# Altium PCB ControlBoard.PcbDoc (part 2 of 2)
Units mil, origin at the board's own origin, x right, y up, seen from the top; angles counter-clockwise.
Board outline 2798 x 1675 mil, 4 copper layers (Top Layer, Layer 1, Layer 2, Bottom Layer), stack 62.493 mil thick; 143 components, 84 nets, 457 pads, 255 vias.
Unrouted connection lines stored in the file: 49.
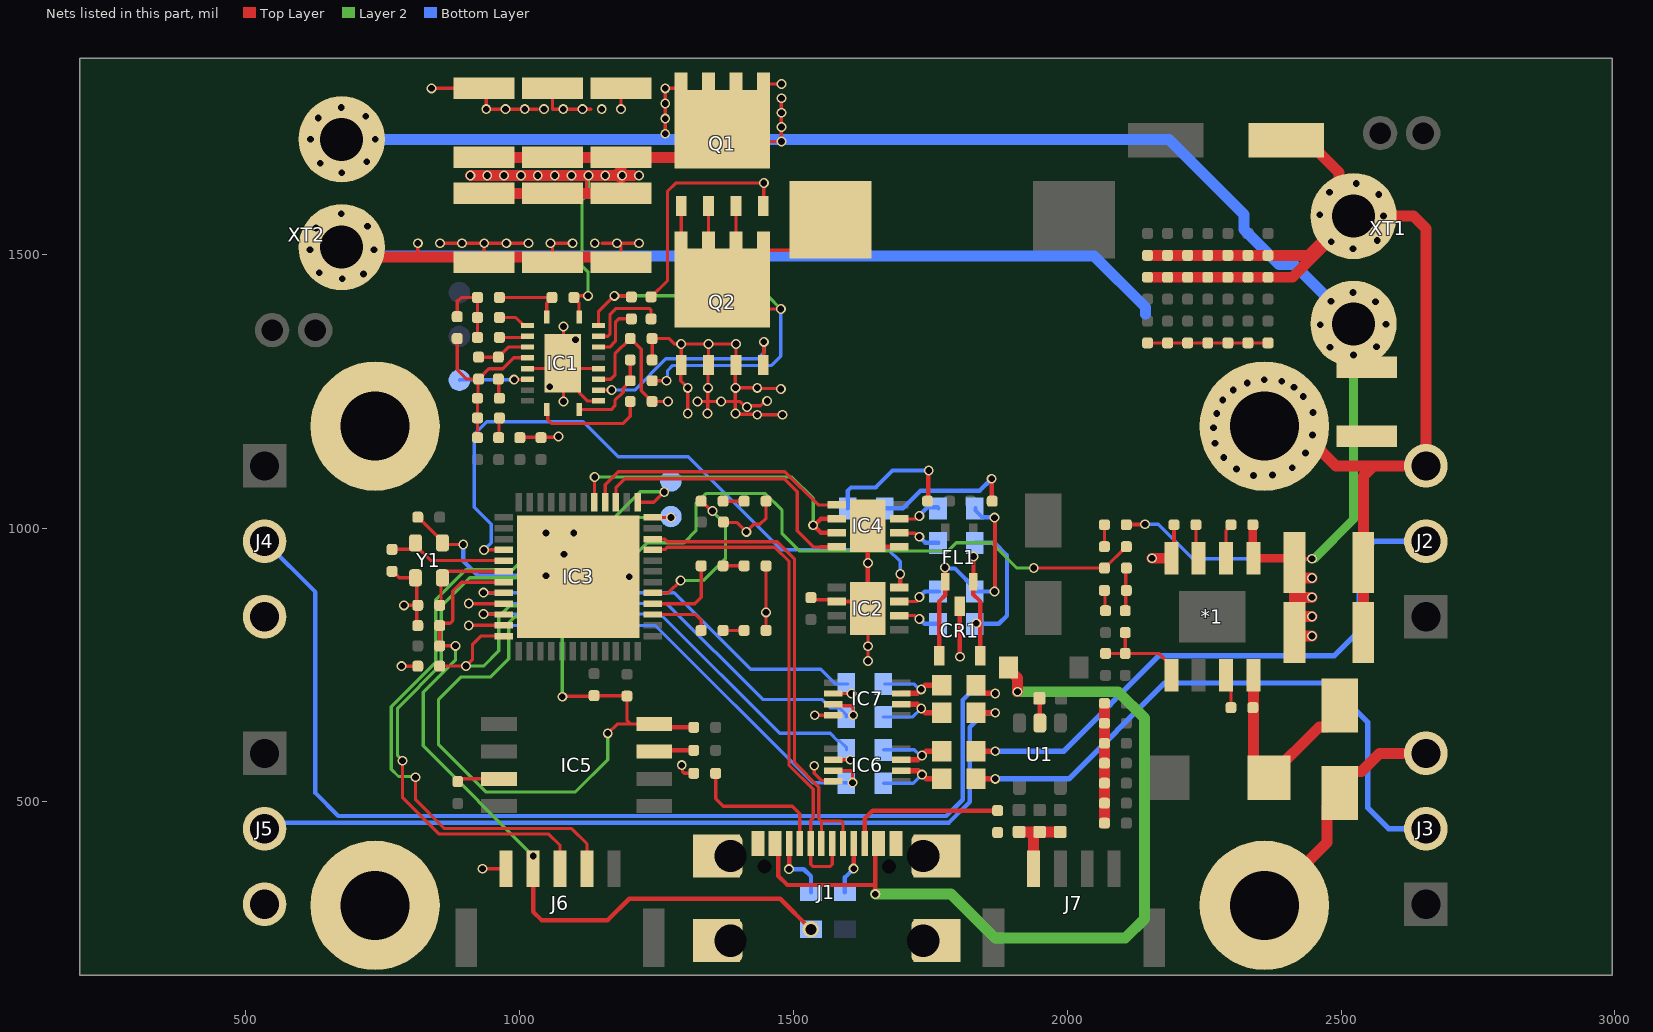
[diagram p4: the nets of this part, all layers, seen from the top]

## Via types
v1: diameter 18, hole 12.3, Top Layer to Bottom Layer, tented both sides, 252 vias
v2: diameter 30, hole 20, Top Layer to Bottom Layer, 2 vias
v3: diameter 20, hole 12.3, Top Layer to Bottom Layer, tented both sides, 1 vias

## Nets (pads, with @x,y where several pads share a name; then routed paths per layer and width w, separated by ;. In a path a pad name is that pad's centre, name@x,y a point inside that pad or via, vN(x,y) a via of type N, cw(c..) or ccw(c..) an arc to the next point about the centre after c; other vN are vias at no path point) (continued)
GND: *1.4 C2.1 C3.1 C5.1 C6.1 C7.1 C8.1 C9.1 C10.1 C11.1 C12.1 C13.1 C14.1 C15.1 C16.1 C17.1 C18.1 C21.1 C24.2 C25.2 C26.1 C27.1 C28.1 C29.1 C30.1 C31.1 C32.1 C33.1 C34.1 C35.1 C36.1 C37.1 C38.1 C39.1 C40.1 C41.1 C42.1 C43.1 C44.1 C45.1 C46.1 C47.2 C48.2 C49.2 C50.2 C51.2 C52.2 C53.2 C54.1 C55.1 C56.1 C57.1 C58.1 C59.2 C60.2 C61.1 C62.2 CR1.3 D2.1 D4.2 D5.2 D6.2 IC1.6 IC1.12 IC1.15 IC1.21 IC2.2 IC2.9 IC3.49 IC4.5 IC4.9 IC5.4 IC6.4 IC7.4 J1.1 J1.2 J1.3 J1.4 J1.17 J1.18 J1.19 J1.20 J2.3 J3.3 J4.3 J5.3 J6.1 J7.1 pad.7 Q2.1 Q2.2 Q2.3 R3.1 R4.2 R5.2 R7.2 R11.2 R13.2 R16.1 R20.1 R23.1 R33.2 U1.2 XT1.2 XT2.2 Y1.2 Y1.4 | length 13063.8
  Top Layer w6: v1(617,1508) 622,1513 XT2.2@663,1513 ; v1(628,1548) XT2.2@663,1513 ; v1(634,1466) XT2.2@675,1507 ; v1(674,1574) 675,1573 XT2.2@675,1513 ; v1(676,1455) 675,1456 XT2.2@675,1504 ; v1(715,1464) XT2.2@675,1504 ; v1(722,1551) XT2.2@684,1513 ; v1(734,1508) 729,1513 XT2.2@684,1513 ; C55.1@767,921 768.08,921 780.08,909 Y1.4@809.79,909 811.89,906.89 C54.1@811.89,858.78 ; v1(784.22,747.78) C62.2@814,747.78 ; v1(788.78,858.78) C54.1@811.89,858.78 ; C59.2@814,821.78 811.89,823.89 C54.1@811.89,858.78 ; C54.1@814,858.78 C54.1@811.89,858.78 ; C52.2@814,1019.78 814.97,1019.78 859,975.75 Y1.2@859,972.78 861.78,970 v1(897,970) ; 814.15,1494.69 v1@814.15,1515.15 ; v1(838.98,1802.98) C12.1@935,1802.98 939,1798.98 v1(939,1765) 1032,1765 ; v1@856,1520 v1@1012,1520 ; R13.2@886,1386 886,1414 893,1421 R7.2@923,1421 R11.2@923,1384.5 C21.1@923,1348 ; v1(932.13,377.87) J6.1@975.36,377.87 ; v1@935,1517 935,1494.69 C14.1@935,1485.01 938,1488.01 C14.1@938,1494.69 ; C61.1@1000.33,1165 1001.33,1166 1070,1166 v1(1071,1167) ; IC1.6@1014.04,1291.16 1069.16,1291.16 IC1.21@1079,1301 ; v1(1055,1258) IC1.21@1079,1282 ; C16.1@1060,1485.01 1060,1494.69 v1@1060,1519 ; v1@1060,1520 v1@1100,1520 ; 1060,1765 1130,1765 ; 1060,1767 C13.1@1060,1802.98 ; v1(1078,692) 1079,693 1135,693 C58.1@1136,694 1136.5,693.5 1195.5,693.5 C57.1@1196,693 1196,649 1203,642 ; v1(1080,1231) IC1.21@1080,1300 ; v1(1080,1368) IC1.21@1080,1322 ; v1(1102,1344) IC1.21@1080,1322 ; IC3.49@1107,911 v1(1200,911) ; IC1.12@1143.96,1232.1 1123.15,1232.1 1109.46,1245.79 1109.46,1270.54 IC1.21@1088.84,1291.16 ; IC1.15@1143.96,1291.16 IC1.21@1088.84,1291.16 ; 1151,1520 v1@1185,1520 ; v1(1161,625) 1178,642 1203,642 ; C15.1@1185,1485.01 v1@1185,1520 ; v1@1185,1766 C18.1@1185,1802.98 ; v1(1218,1520) v1@1185,1520 ; C51.2@1242,1307 C24.2@1242,1346 1273,1346 1283,1336 v1(1295,1336) ; IC5.4@1245.73,642 1203,642 ; Q2.1@1294,1289 1294,1269 v1(1307,1256) v1(1307,1209) ; Q2.1@1294,1297 Q2.1@1295,1298 v1(1295,1336) ; v1(1296,567) 1297.32,565.68 1297.32,555.51 1300.84,552 R23.1@1318,552 ; v1(1325,1231) 1343.5,1231 ; v1(1343,1209) 1343.5,1209.5 1343.5,1231 ; v1(1344,1256) 1343.5,1255.5 1343.5,1231 ; v1@1344,1259 1344,1297 Q2.2@1345,1298 v1(1345,1336) ; C56.1@1372,1010 1397,1010 v1(1414,993) 1427.65,1006.65 1438.65,1006.65 1450,1018 D4.2@1450,1049 ; v1(1394,1209) 1395,1208 1433,1208 v1(1434,1207) v1(1480,1207) ; v1@1394,1214 1394,1231 ; Q2.3@1394,1291 v1(1394,1256) ; Q2.3@1394,1297 Q2.3@1395,1298 1395,1332.49 1391.49,1336 v1(1345,1336) ; D6.2@1450,813 v1(1450,846) D5.2@1450,931 ; v1(1452,1232) 1448.75,1232 1439.85,1223.1 1417.1,1223.1 v1(1415,1221) 1412.49,1221 1402.49,1231 1394,1231 ; v1(1477,1254) 1476,1255 1435,1255 v1(1434,1256) v1(1394,1256) ; C53.2@1532,872 1535.1,868.9 1575.81,868.9 IC2.2@1578.91,865.8 ; v1(1538,566) 1538,552 1551,539 1571.46,539 IC6.4@1572.99,537.47 ; v1(1539,658) 1539.24,658.24 1572.28,658.24 1572.52,658 IC7.4@1572.99,658.47 ; v1(1636,757) v1(1636,784) IC2.9@1636,853 ; R5.2@2106,849 2107,850 2107,926 R33.2@2108,927 ; C36.1@2146.67,1338 C44.1@2183.33,1338 C45.1@2220,1338 C35.1@2256.67,1338 C33.1@2293.33,1338 C34.1@2330,1338 C46.1@2366.67,1338 ; v1(2267,1183) 2270,1186 pad.7@2296,1186 ; v1(2270,1155) pad.7@2301,1186 ; v1(2273,1209) pad.7@2296,1186 ; v1(2284,1234) pad.7@2332,1186 ; v1(2286,1129) pad.7@2343,1186 ; v1(2303,1252) pad.7@2360,1195 ; v1(2309,1108) 2309,1135 pad.7@2360,1186 ; v1(2329,1265) pad.7@2360,1234 ; v1(2360,1271) pad.7@2360,1236 ; v1(2392,1268) pad.7@2360,1236 ; v1(2414,1257) pad.7@2360,1203 ; v1(2431,1240) 2414,1240 pad.7@2360,1186 ; pad.7@2442,1217 pad.7@2411,1186 ; v1(2449,1211) 2424,1186 2418.51,1186 pad.7@2411,1186 ; v1(2461,1572) 2463.31,1569.69 2512.44,1569.69 XT1.2@2522.31,1569.69 ; v1(2479,1613) 2496.27,1595.73 XT1.2@2522.31,1569.69 ; v1(2482,1523) XT1.2@2522.83,1563.83 ; v1(2522,1510) 2522.83,1510.83 XT1.2@2522.83,1563.83 ; v1(2528,1629) 2522.83,1623.83 XT1.2@2522.83,1569.69 ; v1(2566,1525) XT1.2@2522.83,1568.17 ; v1(2569,1609) XT1.2@2529.69,1569.69 ; v1(2577.57,1569.69) XT1.2@2529.69,1569.69 ; XT2.2@663,1513 XT2.2@675,1513 ; XT2.2@675,1504 XT2.2@675,1507 ; XT2.2@675,1507 XT2.2@675,1513 ; XT2.2@675,1513 XT2.2@684,1513 ; IC1.21@1079,1301 1080,1302 IC1.21@1080,1322 ; IC1.21@1079,1301 IC1.21@1080,1300 ; IC1.21@1080,1300 IC1.21@1088.84,1291.16 ; v1(1295,1336) v1(1345,1336) ; 1343.5,1231 v1(1368,1231) 1390,1231 1394,1231 ; 1394,1231 1394,1235 v1(1394,1256) ; pad.7@2296,1186 pad.7@2301,1186 ; pad.7@2301,1186 pad.7@2332,1186 ; pad.7@2332,1186 pad.7@2343,1186 ; pad.7@2343,1186 pad.7@2360,1186 ; pad.7@2360,1186 pad.7@2411,1186 ; pad.7@2360,1186 pad.7@2360,1195 ; pad.7@2360,1195 pad.7@2360,1203 ; pad.7@2360,1203 pad.7@2360,1234 ; pad.7@2360,1234 pad.7@2360,1236 ; XT1.2@2522.31,1569.69 XT1.2@2522.83,1569.69 ; XT1.2@2522.83,1563.83 XT1.2@2522.83,1568.17 ; XT1.2@2522.83,1568.17 XT1.2@2522.83,1569.69 ; XT1.2@2522.83,1569.69 XT1.2@2529.69,1569.69
  Top Layer w8: IC5.4@1245.73,642 1251.73,636 C60.2@1318,636 ; IC2.2@1578.91,865.8 1635.2,865.8 IC2.9@1636,865 ; IC2.9@1636,853 IC2.9@1636,865 ; IC4.9@1636,1004 IC4.9@1636,994.09 ; IC4.5@1693.09,965.61 1664.48,965.61 IC4.9@1636,994.09 ; v1(1804,765) CR1.3@1804,857.25 ; C50.2@1949,689 1949.5,688.5 1949.5,644.56 U1.2@1950,644.06 ; *1.4@2190,944.77 2195,949.77 R4.2@2195,1006 ; IC2.9@1636,865 v1(1636,936) IC4.9@1636,994.09
  Top Layer w20: XT2.2@675,1513 693.31,1494.69 814.15,1494.69 935,1494.69 938,1494.69 1060,1494.69 1175.31,1494.69 C15.1@1185,1485.01 ; C49.2@1912,445 1930.75,445 ; J7.1@1938.18,377.87 1938.18,437.57 1930.75,445 ; C48.2@1987,445 C47.2@1949.5,445 1930.75,445 ; C5.1@2068,461 C6.1@2068,497.5 C7.1@2068,534 C8.1@2068,570.5 C9.1@2068,607 C10.1@2068,643.5 C11.1@2068,680 ; C43.1@2146.67,1458 C42.1@2183.33,1458 C41.1@2220,1458 C40.1@2256.67,1458 C39.1@2293.33,1458 C38.1@2330,1458 C37.1@2366.67,1458 2411.14,1458 2445.94,1492.8 2479.07,1525.93 2517.64,1564.5 XT1.2@2522.83,1569.69 2517.64,1574.89 2496.53,1596 2496.53,1649.11 2437.64,1708 C25.2@2400.24,1708 ; C26.1@2146.67,1498 C27.1@2183.33,1498 C28.1@2220,1498 C29.1@2256.67,1498 C30.1@2293.33,1498 C31.1@2330,1498 C32.1@2366.67,1498 2440.75,1498 2473.87,1531.13 XT1.2@2512.44,1569.69 ; v1(2154.77,944.77) *1.4@2190,944.77 ; pad.7@2360,311 2474.54,425.54 2474.54,492.52 D2.1@2498,515.98 2498,531.73 2521.46,555.2 2537.21,555.2 2570.61,588.59 J3.3@2655,588.59 ; pad.7@2418.51,1186 2441.25,1163.25 2490.92,1113.59 2559.59,1113.59 ; C2.1@2540.99,809 C3.1@2540.99,937 2540.99,1094.99 2559.59,1113.59 ; v1(2577.57,1569.69) 2632.31,1569.69 2655,1547 J2.3@2655,1113.59 2559.59,1113.59
  Layer 2 w6: v1(1078,692) 1078,828 1068,838 991,838 980,827 980,761 947,728 893,728 852,687 852,604 938,518 1102,518 1161,577 v1(1161,625) ; v1(2340,1096) pad.7@2360,1116 ; v1(2375,1097) 2360,1112 pad.7@2360,1116 ; v1(2411,1110) pad.7@2360,1161 ; v1(2435,1137) pad.7@2386,1186 ; v1(2448,1170) 2432,1186 pad.7@2386,1186 ; pad.7@2360,1116 pad.7@2360,1161 ; pad.7@2360,1161 pad.7@2360,1186 pad.7@2386,1186
  Bottom Layer w8: v1(897,970) 897,940 924,913 v1(1048,913) 1048,952 ; v1(1081,952) 1048,952 ; v1(1099,991) v1(1048,991) 1048,952
  Bottom Layer w20: XT2.2@675,1513 691.1,1496.9 2049.1,1496.9 2142.9,1403.1 2142.9,1390.43 ; pad.7@2298.5,1247.5 pad.7@2360,1186
  other v1: 1395,1336 814.15,1520 854.54,1520 894.92,1520 935.31,1520 975.69,1520 1016.08,1520 1056.46,1520 1096.85,1520 1137.23,1520 1177.61,1520 974.14,1765 1009.29,1765 1044.43,1765 1079.57,1765 1114.71,1765 1149.86,1765 1185,1765
LM5146_VCC: C24.1 IC1.14 R15.1 | length 272.6
  Top Layer w6: IC1.14@1143.96,1271.47 1166.47,1271.47 1174,1279 1174,1318 C24.1@1202,1346 1202.5,1346 1222,1326.5 1222,1251 R15.1@1242,1231 v1(1271,1231)
Net*1_2: *1.2 R1.2 | length 65
  Top Layer w6: *1.2@2290,944.77 2290,995.92 2299,1004.92 R1.2@2299,1006
Net*1_3: *1.3 R4.1 | length 63.3
  Top Layer w6: R4.1@2235,1006 2235,949.77 *1.3@2240,944.77
Net*1_5: *1.5 C4.1 R2.2 R5.1 | length 184.6
  Top Layer w6: R2.2@2070,771 C4.1@2106,771 ; R5.1@2106,809 C4.1@2106,771 ; *1.5@2190,731.23 2190,748.45 2167.45,771 C4.1@2106,771
Net*1_7: *1.7 C1.2 | length 63
  Top Layer w6: *1.7@2290,731.23 2299,722.23 C1.2@2299,672
Net*1_8: *1.8 C1.1 D2.2 L1.1 | length 393
  Top Layer w20: *1.8@2340,731.23 2340,572.52 L1.1@2368.52,544 2368.52,544.98 2460.34,636.8 2474.54,636.8 2498,660.27 D2.2@2498,676.02
NetC19_1: C19.1 IC1.17 | length 98.9
  Top Layer w6: IC1.17@1143.96,1330.53 1164.53,1330.53 1175,1341 1175,1376 1181,1382 C19.1@1201,1382
NetC19_2: C19.2 IC1.19 L2.1 Q1.1 Q1.2 Q1.3 Q2.5 Q2.6 Q2.7 Q2.8 Q2.9 R14.2 | length 1328.8
  Top Layer w6: IC1.19@1143.96,1369.9 1143.96,1394.96 v1(1173,1424) 1199,1424 C19.2@1201,1422 ; R14.2@1242,1269 v1(1268,1269) ; Q2.8@1295,1525.87 Q1.1@1295,1588 ; Q2.7@1345,1525.87 Q1.2@1345,1588 ; Q2.9@1361.2,1447 Q2.9@1370,1438.2 ; Q2.6@1395,1525.87 Q1.3@1395,1588 ; v1(1477,1400) 1408.2,1400 Q2.9@1370,1438.2 ; L2.1@1567.56,1563 1511.7,1507.15 1438.95,1507.15 Q2.9@1370,1438.2
  Layer 2 w6: v1(1173,1424) 1453,1424 v1(1477,1400)
  Bottom Layer w6: v1(1268,1269) 1270,1271 1270,1287 1280,1297 1460,1297 1477,1314 v1(1477,1400)
NetC20_1: C20.1 C23.1 IC1.5 R9.2 R12.2 R13.1 | length 316
  Top Layer w6: R13.1@886,1346 886,1289 903,1272 C23.1@925,1272 ; R9.2@923,1165 C20.1@923,1201 R12.2@923,1237 924,1238 924,1271 C23.1@925,1272 ; IC1.5@1014.04,1310.84 988.84,1310.84 969,1291 944,1291 C23.1@925,1272
NetC20_2: C20.2 R8.2 | length 36.6
  Top Layer w6: R8.2@961.67,1165 962.33,1165.67 962.33,1200.33 C20.2@963,1201
NetC21_2: C21.2 IC1.3 | length 52
  Top Layer w6: C21.2@963,1348 1004.94,1348 1007.15,1350.21 IC1.3@1014.04,1350.21
NetC22_1: C22.1 R12.1 | length 35.8
  Top Layer w6: C22.1@961,1272 962,1271 962,1238 R12.1@963,1237
NetC22_2: C22.2 C23.2 IC1.4 | length 96.7
  Top Layer w6: C23.2@925,1312 C22.2@961,1312 979.53,1330.53 IC1.4@1014.04,1330.53
NetC51_1: C51.1 IC1.11 R14.1 | length 164.7
  Top Layer w6: IC1.11@1108.53,1216.35 1167.35,1216.35 1174,1223 1174,1233 1189,1248 1189,1254.92 1203,1268.92 1202,1269.92 C51.1@1202,1307
NetCR1_1: CR1.1 FL1.1 SB2.2 SB4.2 | length 458.3
  Top Layer w8: CR1.1@1766.6,766.75 1766.6,866.6 1777.2,877.2 FL1.1@1777.2,901.93 ; v1(1777,928) 1777.2,927.8 FL1.1@1777.2,901.93 ; FL1.1@1777.41,901.72 FL1.1@1777.2,901.93 ; v1(1867,884) 1868,885 1868,1018 v1@1869,1019
  Bottom Layer w8: v1(1777,928) 1778.91,926.09 1794.91,926.09 1833,888 1833,884 v1(1867,884) ; SB4.2@1832.5,1036 1832.5,1032 1844.5,1020 1868,1020 v1@1869,1019
  other v1: 1867,1019
NetCR1_2: CR1.2 FL1.2 SB3.2 SB5.2 | length 436.3
  Top Layer w8: v1(1829,948) 1828.8,947.8 1828.8,901.93 FL1.2@1828.59,901.72 1828.59,878.41 1841.4,865.6 v1@1841.4,827 ; v1(1834,826) 1835,827 v1@1841.4,827 ; CR1.2@1841.4,766.75 v1@1841.4,827
  Bottom Layer w8: SB3.2@1831.5,825 1875,825 1890,840 1890,950 1867,973 SB5.2@1832.5,973
NetD1_2: D1.2 R3.2 | length 37.8
  Top Layer w6: R3.2@2068,886 2069,885 2069,850 D1.2@2070,849
NetD4_1: D4.1 R21.2 | length 38.5
  Top Layer w6: R21.2@1371.5,1049 D4.1@1410,1049
NetD5_1: D5.1 R22.2 | length 38.5
  Top Layer w6: R22.2@1371.5,931 D5.1@1410,931
NetD6_1: D6.1 R24.2 | length 38.5
  Top Layer w6: R24.2@1371.5,813 D6.1@1410,813
NetIC1_1: IC1.1 R6.1 R7.1 | length 135.3
  Top Layer w6: R7.1@963,1421 R6.1@1059,1421 1059,1419.92 1049.47,1410.39 IC1.1@1049.47,1385.65
NetIC1_2: IC1.2 R11.1 | length 57.1
  Top Layer w6: R11.1@963,1384.5 992.55,1384.5 1007.15,1369.9 IC1.2@1014.04,1369.9
NetIC1_7: IC1.7 TP5.1 | length 125.2
  Top Layer w6: v1(990,1271) 990.24,1271.24 1013.8,1271.24 IC1.7@1014.04,1271.47
  Bottom Layer w6: TP5.1@890,1270 890,1271 v1(990,1271)
NetIC1_10: IC1.10 R15.2 | length 205.3
  Top Layer w6: IC1.10@1049.47,1216.35 1051.39,1214.43 1051.39,1197.61 1056.02,1192.98 1058,1191 1189,1191 1202,1204 R15.2@1202,1231
NetIC1_13: IC1.13 Q2.4 | length 392.7
  Top Layer w6: IC1.13@1143.96,1251.79 1144.07,1251.89 1167.89,1251.89 v1(1168,1252) ; Q2.4@1445,1298 1446,1299 v1(1446,1340)
  Bottom Layer w6: v1(1168,1252) 1210,1252 1267,1309 1435,1309 1446,1320 v1(1446,1340)
NetIC1_18: IC1.18 R10.2 | length 155.2
  Top Layer w6: IC1.18@1143.96,1350.21 1161.39,1350.21 1164.9,1353.73 1164.9,1389.9 1176,1401 1236.49,1401 1240,1397.49 R10.2@1240,1382
NetIC2_6: IC2.6 SB3.1 | length 77.2
  Top Layer w6: IC2.6@1693.09,840.2 1721.8,840.2 1728,834 v1(1730,834)
  Bottom Layer w8: v1(1730,834) 1730.31,834 1739.31,825 SB3.1@1764,825
NetIC2_7: IC2.7 SB2.1 | length 81.7
  Top Layer w6: IC2.7@1693.09,865.8 1724.8,865.8 1730,871 v1(1730,874)
  Bottom Layer w8: v1(1730,874) 1740,884 SB2.1@1765.5,884
NetIC3_27: IC3.27 R24.1 | length 111.6
  Top Layer w6: IC3.27@1242.83,842.1 1320.9,842.1 1331.5,831.5 R24.1@1331.5,813
NetIC3_28: IC3.28 R22.1 | length 151
  Top Layer w6: IC3.28@1242.83,861.79 1319.79,861.79 1331.5,873.5 R22.1@1331.5,931
NetIC3_29: IC3.29 R21.1 | length 283.4
  Top Layer w6: IC3.29@1242.83,881.47 1271.47,881.47 v1(1294,904) ; R21.1@1331.5,1049 1332.58,1049 1350.58,1031 v1(1352,1031)
  Layer 2 w6: v1(1294,904) 1335,904 1376,945 1376,1007 v1(1352,1031)
NetIC4_6: IC4.6 SB5.1 | length 79.5
  Top Layer w6: IC4.6@1693.09,991.2 1693.69,990.6 1722.15,990.6 1728.75,984 v1(1730,984)
  Bottom Layer w8: v1(1730,984) 1741,973 SB5.1@1765,973
NetIC4_7: IC4.7 SB4.1 | length 82.6
  Top Layer w6: IC4.7@1693.09,1016.8 1693.48,1016.4 1724.15,1016.4 1729.75,1022 v1(1730,1022)
  Bottom Layer w8: v1(1730,1022) 1730,1023.31 1744.69,1038 1763,1038 SB4.1@1765,1036
NetIC5_3: IC5.3 R26.1 | length 73.1
  Top Layer w8: IC5.3@1245.73,592 1247.73,594 R26.1@1318,594
NetIC5_7: IC5.7 R25.1 | length 77.3
  Top Layer w6: R25.1@887,537 892,542 IC5.7@962.27,542
NetJ1_7: J1.7 SB7.1 | length 121.2
  Top Layer w8: v1(1492,377) 1492.05,377.05 J1.7@1492.1,423.8 J1.7@1492.1,423.8
  Bottom Layer w8: v1(1492,377) 1519,377 1532,364 SB7.1@1532,335
NetJ1_8: J1.8 R23.2 | length 265.7
  Top Layer w6: R23.2@1358,552 1358,506 1372,492 1498,492 1511.79,478.21 J1.8@1511.79,423.8
NetJ1_13: J1.13 SB6.1 | length 95.5
  Top Layer w8: v1(1610,378) 1610.11,378.11 1610.11,423.7 J1.13@1610.21,423.8
  Bottom Layer w8: SB6.1@1594,335 1594,362 v1(1610,378)
NetJ1_14: J1.14 R20.2 | length 294.5
  Top Layer w8: J1.14@1629.9,423.8 1629.9,468.9 1645,484 R20.2@1873,484
NetJ2_2: J2.2 R27.2 | length 1060.6
  Top Layer w10: R27.2@1833.5,592.33 v1(1868.67,592.33)
  Bottom Layer w10: v1(1868.67,592.33) 1993.33,592.33 2168,767 2488,767 2533,812 2533,949 2559.8,975.8 J2.2@2655,975.8
NetJ3_2: J3.2 R28.2 | length 1092
  Top Layer w10: R28.2@1833.5,542 v1@1865,542
  Bottom Layer w10: v1(1868.67,542) 2003,542 2178,717 2477,717 2549,645 2549,489 2587.2,450.8 J3.2@2655,450.8
NetJ4_2: J4.2 R29.2 | length 1997.4
  Top Layer w10: R29.2@1833.5,713 1833.5,712.72 1848.21,698 v1@1868,698
  Bottom Layer w8: J4.2@534.25,975.8 627,883.05 627,516 668.81,474.19 1779.19,474.19 1809,504 1809,686 1821,698 v1(1868.67,698)
NetJ5_2: J5.2 R30.2 | length 1536.1
  Top Layer w10: R30.2@1833.5,662.67 v1@1867.67,662.67
  Bottom Layer w8: J5.2@534.25,450.8 545.55,462.09 766.91,462.09 1784.2,462.09 1822,499.89 1822,636 1847.67,661.67 1867.67,661.67 v1(1868.67,662.67)
NetQ1_4: Q1.4 R10.1 | length 430.1
  Top Layer w6: R10.1@1240,1422 1270,1452 1270,1615 1285,1630 v1(1446,1630) 1446,1589 Q1.4@1445,1588
NetR17_2: R17.2 SB1.1 | length 258.6
  Top Layer w8: v1(1862,1090) 1862.5,1089.5 1862.5,1049.5 R17.2@1862.9,1049.1
  Bottom Layer w8: SB1.1@1667,1036 1700,1036 1732,1068 1840,1068 v1(1862,1090)
NetR18_1: R18.1 SB1.2 | length 260.9
  Top Layer w8: R18.1@1745,1049 1746,1050 1746,1104 v1(1747,1105)
  Bottom Layer w8: SB1.2@1599.5,1036 1599.5,1068.36 1605.14,1074 1650,1074 1681,1105 ; 1690,1105 1681,1105 ; v1(1747,1105) 1681,1105
NetR31_2: R31.2 R32.1 | length 40
  Top Layer w6: R32.1@2068,966 R31.2@2068,1006
RESET: C59.1 IC3.7 J6.2 R19.2 SB7.2 | length 1371
  Top Layer w6: v1(882.78,784.78) R19.2@854,784.78 C59.1@854,821.78 858.22,826 873,826 878,831 878,885 894.16,901.16 IC3.7@971.17,901.16
  Top Layer w8: J6.2@1024.57,377.87 1024.57,299.43 1040,284 1161,284 1200,323 1476,323 v2(1532,267)
  Layer 2 w6: v1(882.78,784.78) 882.78,758.78 824,700 824,602 v1(1025,401)
  Bottom Layer w8: v2(1532,267) SB7.2@1532,267.5
RS485_DIR: IC3.41 IC4.2 IC4.3 | length 606.6
  Top Layer w6: IC3.41@1136.53,1046.83 1136.76,1047.06 1136.76,1092.76 v1(1137,1093)
  Top Layer w8: v1(1536,1005) v1@1536.39,1005 ; IC4.3@1578.91,991.2 1550.18,991.2 v1@1536.39,1005 ; IC4.2@1578.91,1016.8 1578.81,1016.9 1550.18,1016.9 1538.28,1005 v1@1536.39,1005
  Layer 2 w6: v1(1137,1093) 1497,1093 1536,1054 v1(1536,1005)
RS485_RX: IC3.40 IC4.1 | length 490.2
  Top Layer w6: IC3.40@1156.21,1046.83 1156.21,1079.21 1180,1103 1484.28,1103 1545.09,1042.19 IC4.1@1578.72,1042.19
  Top Layer w8: IC4.1@1578.72,1042.19 IC4.1@1578.91,1042.39
RS485_TX: IC3.39 IC4.4 | length 530.1
  Top Layer w6: IC3.39@1175.9,1046.83 1175.9,1073.9 1192,1090 1483,1090 1507,1066 1507,995 1536.69,965.31 1549,965.31
  Top Layer w8: 1549,965.31 1578.61,965.31 IC4.4@1578.91,965.61
STB_1: IC2.8 IC3.4 | length 1207
  Top Layer w6: v1(935,960) 935.11,960.11 971.07,960.11 IC3.4@971.17,960.21
  Top Layer w8: IC2.8@1693.09,891.39 1695,893.3 v1(1695,916)
  Bottom Layer w6: v1(935,960) 948,973 948,1007 917,1038 917,1171 939.9,1193.9 1115.82,1193.9 1179.72,1130 1308,1130 1477.5,960.5 1673.5,960.5 1695,939 v1(1695,916)
SWCLK: IC3.37 J6.4 TP6.1 | length 1381.7
  Top Layer w6: v1(810,545) 810,504 862.8,451.2 1094.8,451.2 1123,423 J6.4@1123,377.87 ; IC3.37@1215.27,1046.83 1244.83,1046.83 v1(1264,1066)
  Layer 2 w6: v1(810,545) 808.77,546.23 778.77,546.23 765.49,559.51 765.49,673.49 847,755 847,869 902,924 987,924 1031.1,968.1 1122.1,968.1 1220,1066 v1(1264,1066)
SWDIO: IC3.36 J6.3 TP7.1 | length 1280.6
  Top Layer w6: v1(786,575) 786,508 852.9,441.1 1052.9,441.1 1073.79,420.21 J6.3@1073.79,377.87 ; IC3.36@1242.83,1019.27 v1(1276.27,1019.27)
  Layer 2 w6: v1(786,575) 786,575.51 777,584.51 777,670.72 857.1,750.82 857.1,856.82 909.28,909 993,909 1016,932 1116,932 1203.27,1019.27 v1(1276.27,1019.27)
  Bottom Layer w6: v1(1276.27,1019.27) 1279.51,1019.27 TP7.1@1283.19,1022.94
USB_CAN_DM: IC3.33 J1.9 J1.11 | length 916
  Top Layer w6: IC3.33@1242.83,960.21 1243.26,960.65 1265.04,960.65 1269.29,964.9 1466.1,964.9 1491.9,939.1 1491.9,566.82 1536,522.72 1536,470.81 1531.47,466.28 J1.9@1531.47,423.8 1531.47,385.51 1534.99,382 1567.33,382 1570.84,385.51 J1.11@1570.84,423.8
USB_CAN_DP: IC3.34 J1.10 J1.12 | length 892.6
  Top Layer w6: IC3.34@1242.83,979.9 1265.37,979.9 1270.27,975 1470.28,975 1502,943.28 1502,571 1546.1,526.9 1546.1,469.97 1551.16,464.91 ; J1.10@1551.16,423.8 1551.16,464.91 ; J1.12@1590.53,423.8 1590.53,461.4 1587.01,464.91 1551.16,464.91
V_POWER_IN: C62.1 IC3.12 R32.2 R33.1 | length 1669.9
  Top Layer w6: C62.1@852.24,748 v1(902,748) 914,760 914,788 928.73,802.73 IC3.12@971.17,802.73 ; v1(1939,927) 2036,927 R33.1@2068,927 2068.5,927 2107.5,966 R32.2@2108,966
  Layer 2 w6: v1(902,748) 934,748 962,776 962,838 982,858 1118,858 1233,973 1300.24,973 1322,994.76 1322,1044.76 1340.24,1063 1449,1063 1479,1033 1479,990.5 1511.5,958 1782,958 1797,973 1862,973 1908,927 v1(1939,927)
VBUS: D3.1 J1.5 J1.6 J1.15 J1.16 | length 1556.3
  Top Layer w6: J1.5@1460.61,423.8 J1.6@1472.42,423.8
  Top Layer w8: J1.6@1472.42,423.8 1472.42,364.58 1489,348 1649.58,348 ; v1(1649.58,331.42) J1.15@1649.58,423.8
  Top Layer w20: D3.1@1892.63,745 1892.63,742.24 1909,725.87 v1(1909,701)
  Layer 2 w20: v1(1649.58,331.42) 1787.58,331.42 1868,251 2106,251 2141,286 2141,653 2093,701 v1(1909,701)
VIN: *1.1 C2.2 C3.2 C12.2 C13.2 C14.2 C15.2 C16.2 C17.2 C18.2 IC1.20 Q1.5 Q1.6 Q1.7 Q1.8 Q1.9 R1.1 R6.2 R31.1 XT1.1 XT2.1 | length 6271.8
  Top Layer w6: v1(632,1749) 635.85,1749 XT2.1@635.85,1666.15 ; XT2.1@675,1708 XT2.1@675.93,1708.93 ; XT2.1@675,1709.85 XT2.1@675.93,1708.93 ; v1(719,1752) 678.35,1711.35 XT2.1@675.93,1708.93 ; v1(721,1669) 715.85,1669 XT2.1@675.93,1708.93 ; IC1.20@1108.53,1385.65 1108.53,1410.39 1099,1419.92 R6.2@1099,1421 1102,1424 v1(1125,1424) ; v1@1122,1641 1122.5,1640.5 1122.5,1610.99 ; C15.2@1185,1610.99 v1@1185,1639.15 ; v1(1266,1720) v1(1266,1803) 1266.13,1803.13 1286.19,1803.13 1295,1811.94 Q1.8@1295,1815.87 ; Q1.9@1370,1728.2 1392.2,1706 v1(1478,1706) v1@1478,1782 ; Q1.5@1445,1815.87 1449.87,1811 v1(1478,1811) ; C3.2@2415.01,937 2422.01,944 v1(2447.01,944) ; v1(2462,1371) 2474.67,1371 XT1.1@2497.83,1347.84 ; XT1.1@2466.84,1372.84 2466.84,1374.84 XT1.1@2493.84,1401.84 ; XT1.1@2474.67,1372.84 XT1.1@2522.83,1372.84 ; v1(2479.99,1330) XT1.1@2497.83,1347.84 ; v1(2481.68,1414) XT1.1@2493.84,1401.84 ; v1(2522,1430) XT1.1@2493.84,1401.84 ; XT1.1@2522.83,1316 2522.83,1294.27 C17.2@2523,1294.1 ; XT1.1@2522.83,1322.67 XT1.1@2522.83,1322.83 ; v1(2523,1316) 2523,1322.67 XT1.1@2522.83,1322.83 ; v1(2562.99,1413) XT1.1@2522.83,1372.84 ; v1(2564.68,1331) XT1.1@2522.83,1372.84 ; v1(2582,1372) 2581.16,1372.84 XT1.1@2522.83,1372.84 ; XT1.1@2493.84,1401.84 XT1.1@2522.83,1372.84 ; XT1.1@2497.83,1347.84 XT1.1@2522.83,1322.83 ; XT1.1@2497.83,1347.84 XT1.1@2522.83,1372.84 ; XT1.1@2522.83,1322.83 XT1.1@2522.83,1372.84
  Top Layer w8: R31.1@2108,1006 2108.5,1006.5 2141.5,1006.5 v1(2142,1007)
  Top Layer w16: R1.1@2339,1006 2339,945.77 *1.1@2340,944.77 C3.2@2407.24,944.77
  Top Layer w20: v1(617.85,1709.85) 617.85,1684.15 v1(636,1666) ; XT2.1@635.85,1666.15 v1(636,1666) ; v1(674,1768) 675,1767 675,1714.7 678.35,1711.35 679.85,1709.85 v1(736.15,1709.85) ; v1(675,1649) 658,1666 v1(636,1666) ; XT2.1@675,1705 v1(636,1666) ; v1(910,1644) 1175.77,1644 ; C14.2@935,1610.99 C16.2@1060,1610.99 1122.5,1610.99 C15.2@1185,1610.99 ; C12.2@935,1677 C13.2@1060,1677 C18.2@1185,1677 ; v1@1185,1639.15 v1@1185,1644 ; 1208,1644 v1@1185,1644 ; Q1.9@1370,1728.2 1355.14,1728.2 1303.94,1677 1194.69,1677 1185,1667.31 1185,1653.23 ; C3.2@2415.01,937 C3.2@2415.01,914 ; v1(2447.01,803) 2421.01,803 C2.2@2415.01,809 C2.2@2415.01,828.56 ; v1(2447.01,838.25) 2424.69,838.25 C2.2@2415.01,828.56 ; v1(2447.01,873.5) 2416.51,873.5 2415.01,875 ; v1(2447.01,908.75) 2420.26,908.75 C3.2@2415.01,914 ; 1175.77,1644 v1@1185,1644 ; 1175.77,1644 1185,1653.23 ; v1@1185,1644 1185,1653.23 ; C2.2@2415.01,828.56 2415.01,875 ; 2415.01,875 C3.2@2415.01,914
  Layer 2 w6: v1(1125,1424) 1125,1467 1114,1478 1114,1599.03 1125.6,1610.63 v1(1125.6,1644)
  Layer 2 w16: v1@2451,944 2522.83,1015.83 XT1.1@2522.83,1316 ; v1(2462,1371) 2474.67,1371 XT1.1@2522.83,1322.83 ; XT1.1@2522.83,1322.67 XT1.1@2522.83,1322.83 ; XT1.1@2522.83,1372.84 XT1.1@2522.83,1322.83 ; v1(2523,1316) 2523,1322.67 XT1.1@2522.83,1322.83
  Bottom Layer w6: v1(2142,1007) 2166,1007 2229,944 v1(2447.01,944)
  Bottom Layer w20: v1(636,1666) 679.85,1709.85 v1(736.15,1709.85) 1478,1709.85 2185.83,1709.85 2322.9,1572.78 2322.9,1545.43 2386.74,1481.59 2414.09,1481.59 v1(2481.68,1414) XT1.1@2522.83,1372.84 2520.99,1371 v1(2462,1371)
  other v1: 940.8,1644 971.6,1644 1002.4,1644 1033.2,1644 1064,1644 1094.8,1644 1156.4,1644 1187.2,1644 1218,1644 1478,1732.25 1266,1747.67 1478,1758.5 1266,1775.33 1478,1784.75
WS2812_A: IC3.10 IC6.2 SB8.1 | length 836.5
  Top Layer w6: v1(934,843) 934.45,842.55 970.72,842.55 IC3.10@971.17,842.1 ; IC6.2@1572.99,576.84 v1(1603.84,576.84)
  Bottom Layer w6: v1(934,843) 1257,843 1475,625 1567,625 1580,612 1584,612 1597,599 SB8.1@1597,595
WS2812_B: IC3.11 IC6.3 SB10.1 | length 939.3
  Top Layer w6: v1(907,822) 907.21,822.21 970.96,822.21 IC3.11@971.17,822.42 ; IC6.3@1572.99,557.16 1604.49,557.16 1608,553.64 v1(1608,535)
  Bottom Layer w6: v1(907,822) 1248,822 1535,535 v1(1608,535)
WS2812_C: IC3.8 IC7.2 SB9.1 | length 804.9
  Top Layer w6: v1(934,882) 934.26,881.74 970.91,881.74 IC3.8@971.17,881.47 ; IC7.2@1572.99,697.84 v1(1605.84,697.84)
  Bottom Layer w6: v1(934,882) 1282,882 1422,742 1550,742 1577,715 SB9.1@1599.5,715
WS2812_CHAN_A: IC6.7 R27.1 SB8.2 | length 154.3
  Top Layer w10: IC6.7@1697.01,576.84 1726.84,576.84 v1(1734.59,584.59) 1742.33,592.33 R27.1@1770.5,592.33
  Bottom Layer w6: SB8.2@1664.5,595 1720.93,595 1731.34,584.59 v1(1734.59,584.59)
WS2812_CHAN_B: IC6.6 R28.1 SB10.2 | length 156.3
  Top Layer w10: IC6.6@1697.01,557.16 1727.84,557.16 1743,542 R28.1@1770.5,542
  Bottom Layer w6: SB10.2@1664.5,534 1719.01,534 v1(1734.59,549.58)
WS2812_CHAN_C: IC7.7 R29.1 SB9.2 | length 150.2
  Top Layer w10: IC7.7@1697.01,697.84 1725.84,697.84 v1(1733.42,705.42) 1741,713 R29.1@1770.5,713
  Bottom Layer w6: SB9.2@1667,715 1720.6,715 1730.17,705.42 v1(1733.42,705.42)
WS2812_CHAN_D: IC7.6 R30.1 SB11.2 | length 155.7
  Top Layer w10: IC7.6@1697.01,678.16 1725.84,678.16 1741.33,662.67 R30.1@1770.5,662.67
  Bottom Layer w6: SB11.2@1664,655 1718.01,655 v1(1733.42,670.41)
WS2812_D: IC3.9 IC7.3 SB11.1 | length 893.8
  Top Layer w6: v1(907,862) 907.11,861.89 971.07,861.89 IC3.9@971.17,861.79 ; IC7.3@1572.99,678.16 1575.9,675.25 1604.75,675.25 1608.77,671.23 1608.77,658.23 v1(1609,658)
  Bottom Layer w6: v1(907,862) 1269,862 1444,687 1552,687 1567,672 1583.5,672 1596.5,659 SB11.1@1596.5,655
XT_G4_IN: C54.2 IC3.6 Y1.1 | length 170.8
  Top Layer w6: C54.2@854,858.78 856.5,861.28 856.5,906.5 Y1.1@859,909 859,911.36 868.48,920.84 IC3.6@971.17,920.84
XT_G4_OUT: C55.2 IC3.5 Y1.3 | length 223.7
  Top Layer w6: C55.2@767,961 800.37,961 Y1.3@809.79,970.41 ; Y1.3@809.79,972.78 Y1.3@809.79,970.41 ; IC3.5@971.17,940.53 838.1,940.53 809.79,968.84 Y1.3@809.79,970.41
pads on no net: *1.6 *1.9 IC1.8 IC1.9 IC1.16 IC3.17 IC3.18 IC3.19 IC3.25 IC3.26 IC3.30 IC3.31 IC3.32 IC3.38 IC3.42 IC3.43 IC3.44 IC3.45 J1.MH1 J1.MH2 J6.6 J6.7 J7.5 J7.6 U1.4
copper on no net: | length 165
  Top Layer w20: v1(2177,838) 2265,838 v1(2342,838)

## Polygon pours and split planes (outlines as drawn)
GND on Bottom Layer "ya" (solid, remove dead copper, pour order 9): 169,1899 3015,1899 3015,115 152,115 152,119
GND on Bottom Layer "GND_L04_P001" (solid, remove dead copper, pour order 1): 574,1614 574,1401 594,1381 1909.11,1381 2188.1,1102.01 2188.1,1024.9 2219,994 2498,994 2552.9,1048.9 2552.9,1163.9 2594,1205 2555,1244 2472,1244 2102,1614 589,1614
GND on Bottom Layer "GND_L04_P003" (solid, remove dead copper, pour order 3): 1475,1309 1267,1309 1210,1252 1142,1252 1140,1250 1217,1173 1217,1158 1774,1158 1785,1169 1833,1169 1847,1155 2135.11,1155 2135.11,1260.11 2150,1275 1991,1434 1475,1434
VIN on Bottom Layer "VIN_L04_P000" (solid, remove dead copper, pour order 0): 574,1614 2102,1614 2511,1205 2594,1205 2679,1290 2679,1613.53 2571.26,1721.27 2572,1722.01 2572,1874 574,1874
5VDC_LED on Layer 2 "5VDC_LED_L03_P006" (solid, remove dead copper, pour order 6): 176,1905 3040,1905 3040,89 175,89
3V3 on Layer 2 "3V3_L03_P004" (solid, remove dead copper, pour order 4): 943,1102 887.84,1102 629,843.16 629,509 852,286 1295,286 1361,352 1361,529 1376,544 1492.5,544 1496,540.5 1496,489 1523,462 1967,462 2038,391 2078,391 2095,408 2095,565 2039,621 1682.69,621 1554.69,749 1434,749 1376,807 1376,1007 1352,1031 1315,1031 1314,1032 1314,997 1304,987 1240,987 1240,1042 1264,1066 1264,1091 1139,1091 1104,1126 966,1126 955,1115
5VDC on Layer 2 "5VDC_L03_P005" (solid, remove dead copper, pour order 5): 1314,1032 1314,1047 1330,1063 1449,1063 1479,1033 1479,990.5 1516.5,953 1668,953 1668,1133 2009,1133 2013,1129 2013,1013 2079,1013 2095,997 2095,839 2048,792 1755,792 1704,741 1706.61,738.39 1706.61,607.9 1584.1,607.9 1470,722 1412.06,722 1295.06,839 1314,844
GND on Layer 1 "GND_L02_P008" (solid, remove dead copper, pour order 8): 155,1911 3039,1911 3039,109 155,109
VIN on Layer 1 "VIN_L02_P007" (solid, remove dead copper, pour order 7): 568,1840 568,1608 1940,1608 2244,1304 2411,1304 2474,1241 2599,1241 2656,1298 2656,1447 2621,1482 2490,1482 2060,1912 567,1912
GND on Top Layer "GND_L01_P011" (solid, remove dead copper, pour order 11): 175,1893 175,89 3050,89 3050,1893
5VDC_LED on Top Layer "5VDC_LED_L01_P010" (solid, remove dead copper, pour order 10): 2239.58,1663.71 2247,1671.13 2247,1746 2763,1746 2862,1647 2862,1076 2713,927 2556,927 2536,907 2544,899 2544,120 2549,125 3178,125 3178,1805 3005,1978 2941,1914 2122,1914 2059,1851 2059,1640

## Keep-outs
Keep-Out Layer:
  the board outline again, w1

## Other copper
Top Layer:
  region net VIN: 1449.87,1811 1478,1811 1478,1705 1444,1705
  region net GND: 2479.13,1666.5 2440.63,1628 2433,1628 2433,1595 2408,1570 2410,1568 2552,1568 2615,1631 2615,1656 2603,1668
  region net GND: 580,1602 632,1602 637,1607 735,1607 793,1549 793,1429 743,1379 677,1379 639,1417 552,1417 518,1451
  region net GND: 1295,1336 1291,1332 1291,1258 1392,1258 1394,1256 1395,1257 1395,1336
  region net 5VDC_LED: 2238,1725 2238,1778 2236,1780 2227,1771 2106,1771 2087,1752 2087,1692 2165,1692 2172,1685
  region net NetC19_2: 1446,1384 1513,1384 1519,1390 1519,1451 1485,1451 1473,1463 1466,1456 1436,1456
  region net NetC19_2: 1402,1582 1402,1575 1451,1526 1451,1502 1393,1502 1368,1527 1368,1560 1367,1561
  region net VIN: 1255,1770 1165,1680 1187,1658 1257,1658
  region net VIN: 1277.5,1830 1440,1830 1446,1824 1441,1819 1441,1782 1331,1782 1322,1773 1319,1776 1288,1776
  region net VIN: 1231,1601 1230,1602 1230,1610 1252,1610 1306,1664 1306,1691 1257,1691 1247,1701 1230,1684 1206,1684
  region net VIN: 1183,1694 1207,1694 1253,1740 1253,1820 1263,1830 1292,1830 1292,1818.87 1303.94,1806.93 1303.94,1677 1232,1677 1229,1674
  region net VIN: 905,1695 887,1695 783,1799 609,1799 574,1764 574,1652 610,1616 763,1616 787,1592 1188,1592 1197,1601 1196.5,1601.5 1196.5,1644
  region net VIN: 2419,992 2458,992 2458,754 2415.01,754 2415.01,894.5
  region net VIN: 925,1677 928,1674 1229,1674 1231,1672 1230,1671 1230,1610 897,1610 894,1607 888,1613 888,1677
  region net GND: 2146.67,1498 2146.67,1458 2411.14,1458 2411.14,1468.4 2440.75,1498
  region net VIN: 2595,1288 2597,1290 2597,1360 2566,1360 2544,1338 2544,1323
  region net 5VDC_LED: 2130.13,1733.13 2023,1626 2023,1593.43 2154.43,1593.43 2159,1598
  region net 5VDC_LED: 2241,1688 2241,1581 2367,1581 2378,1570 2378,1528 2076,1528 2056,1548 2077.24,1569.24 2077.24,1644.24 2133,1700
  region net 5VDC_LED: 1938,1510 1938,1126 1923,1111 1923,1016 1974,965 2025,965 2033,973 2033,1044.33 2113,1124.33 2113,1348 2134,1369 2357.67,1369 2366.67,1378 2366.67,1418 2129,1418 2113,1434 2113,1514 2133,1534 2074,1534 2064,1544 1987,1544
  region net GND: 2412.34,1206 2604,1206 2636,1238 2636,1421 2550,1507 2550,1643 2812,1643 2861,1594 2861,1082 2801,1022 2377,1022 2309.28,1089.72
  region net VIN: 2492,1314 2492,1275 2575,1275 2578,1275 2578,1349
  region net NetC19_2: 1398,1534 1398,1541 1642,1541 1642,1448 1379,1448
  region net NetC19_2: 1296,1599 1296,1486 1399,1486 1399,1599
  pour cut-out: 2170,647 2170,441 2383,441 2383,647
  pour cut-out: 1519,1832 1519,1287 2059,1287 2059,1833
Layer 1:
  pour cut-out: 2170,647 2170,441 2383,441 2383,647
Layer 2:
  region net VIN: 2501,1317 2502,1316 2502,1042 2414,954 2414,777 2430,761 2457,761 2570,874 2570,1345
  pour cut-out: 2170,647 2170,441 2383,441 2383,647
  pour cut-out: 1519,1832 1519,1287 2059,1287 2059,1833
Bottom Layer:
  region net VIN: 578,1813 580,1811 580,1656 620,1616 695,1616 695,1668.7 736.15,1709.85 712,1734 712,1820
  region net GND: 674,1609 672,1607 593,1607 593,1587 547,1541 547,1467 599,1415 699,1415 700,1416
  region net VIN: 2503,1471 2505,1469 2619,1469 2619,1444 2637,1426 2637,1313 2597,1273 2597,1265 2499,1265 2490,1256
  region net GND: 2395.42,1314.31 2488.31,1221.42 2488.31,1212.69 2508,1193 2508,1101 2442,1035 2278,1035 2214,1099 2214,1234 2211,1237 2223,1249 2223,1301 2230,1301 2257,1328
  region net VIN: 2521,1477 2521,1266 2514,1273 2463,1273 2400,1336 2400,1457 2396,1461
  region net GND: 674,1609 674,1416 678,1412 746,1412 803,1469 803,1583
  region net VIN: 672,1811 672,1629.11 683.11,1618 732,1618 732,1619 814,1701 793,1722 793,1778
  pour cut-out: 2170,647 2170,441 2383,441 2383,647

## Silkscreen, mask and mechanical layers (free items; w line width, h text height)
Bottom Overlay:
  text "48V FDCAN" at 323,1769.93 h80 r90
  text "48V FDCAN" at 2906,1769.93 h80 r90
  text "CHANEL C" at 323,1144.93 h80 r90
  text "CHANEL A" at 2906,1128.93 h80 r90
  text "120R" at 1565.94,1018 h60
  text "RS485" at 2022,1018 h60
  text "FDCAN" at 2022,867 h60
  text "A" at 1569.94,701 h60
  text "B" at 1570,639 h60
  text "CHANEL B" at 2906,610.93 h80 r90
  text "CHANEL D" at 326,606.93 h80 r90
  text "C" at 1569.94,580 h60
  text "D" at 1570,518 h60
Top Solder:
  text "Breathing LED" at 1201,1131 h75
Bottom Solder:
  region: 1399 vertices and 6 holes, not listed, extent 1262.7,1499.65 1385.23,1602.67
  text "Breathing LED" at 2111,1518.11 h120
  text "--------------------------" at 2110.93,1466.35 h80
  text "v1.0" at 1330.41,1425 h40
  text "Designed by Tien Thinh in VinMotion" at 2110.96,1425.29 h40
